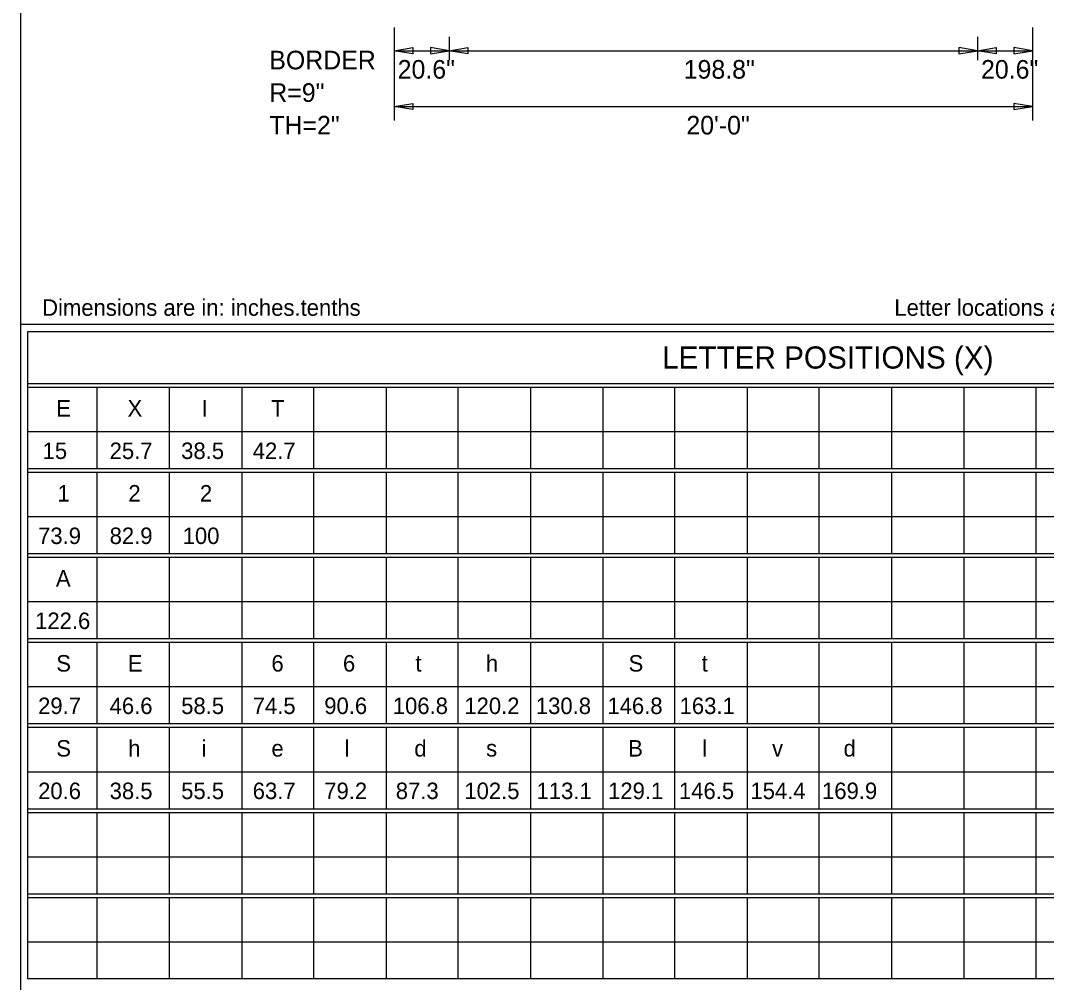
# Model space of a CAD drawing. Extents: x 2149934 to 2150188, y 145113 to 145238.
# Drawn here: x 2150076.32 to 2150108.47, y 145167.07 to 145197.23 of the extents above; entities that cross this region are included whole.
import ezdxf

# ---------------------------------------------------------------- set-up
doc = ezdxf.new("R2010")
doc.units = 0
doc.layers.add('GSDIMS', color=7, linetype='Continuous')
doc.layers.add('Level 1', color=7, linetype='Continuous')

msp = doc.modelspace()

# ---------------------------------------------------------------- linework, layer by layer
at = {"layer": 'GSDIMS'}
for p, q in [((2150088.029, 145197.007), (2150088.029, 145194.09)), ((2150108.029, 145197.007), (2150108.029, 145194.09)), ((2150088.029, 145196.715), (2150088.029, 145195.986)), ((2150089.747, 145196.715), (2150089.747, 145195.986)), ((2150089.747, 145196.715), (2150089.747, 145195.986)), ((2150106.31, 145196.715), (2150106.31, 145195.986)), ((2150106.31, 145196.715), (2150106.31, 145195.986)), ((2150108.029, 145196.715), (2150108.029, 145195.986)), ((2150088.029, 145196.278), (2150089.747, 145196.278)), ((2150089.747, 145196.278), (2150106.31, 145196.278)), ((2150106.31, 145196.278), (2150108.029, 145196.278)), ((2150088.029, 145194.965), (2150088.029, 145194.236)), ((2150108.029, 145194.965), (2150108.029, 145194.236)), ((2150088.029, 145194.528), (2150108.029, 145194.528))]:
    msp.add_line(p, q, dxfattribs=at)
for points in [[(2150088.029, 145196.278), (2150088.612, 145196.375), (2150088.612, 145196.181)], [(2150089.747, 145196.278), (2150089.164, 145196.375), (2150089.164, 145196.181)], [(2150089.747, 145196.278), (2150090.331, 145196.375), (2150090.331, 145196.181)], [(2150106.31, 145196.278), (2150105.727, 145196.375), (2150105.727, 145196.181)], [(2150106.31, 145196.278), (2150106.893, 145196.375), (2150106.893, 145196.181)], [(2150108.029, 145196.278), (2150107.445, 145196.375), (2150107.445, 145196.181)], [(2150088.029, 145194.528), (2150088.612, 145194.625), (2150088.612, 145194.431)], [(2150108.029, 145194.528), (2150107.445, 145194.625), (2150107.445, 145194.431)]]:
    msp.add_lwpolyline(points, close=True, dxfattribs=at)
at = {"layer": 'Level 1'}
for p, q in [((2150076.316, 145216.512), (2150076.316, 145117.388)), ((2150076.316, 145187.705), (2150121.342, 145187.705)), ((2150076.548, 145185.849), (2150134.843, 145185.849)), ((2150076.548, 145185.733), (2150134.843, 145185.733)), ((2150078.704, 145185.733), (2150078.704, 145183.183)), ((2150080.977, 145185.733), (2150080.977, 145183.183)), ((2150083.25, 145185.733), (2150083.25, 145183.183)), ((2150085.499, 145185.733), (2150085.499, 145183.183)), ((2150087.772, 145185.733), (2150087.772, 145183.183)), ((2150090.021, 145185.733), (2150090.021, 145183.183)), ((2150092.294, 145185.733), (2150092.294, 145183.183)), ((2150094.566, 145185.733), (2150094.566, 145183.183)), ((2150096.816, 145185.733), (2150096.816, 145183.183)), ((2150099.088, 145185.733), (2150099.088, 145183.183)), ((2150101.337, 145185.733), (2150101.337, 145183.183)), ((2150103.61, 145185.733), (2150103.61, 145183.183)), ((2150105.883, 145185.733), (2150105.883, 145183.183)), ((2150108.132, 145185.733), (2150108.132, 145183.183)), ((2150076.548, 145184.342), (2150126.185, 145184.342)), ((2150076.548, 145183.183), (2150134.843, 145183.183)), ((2150076.548, 145183.067), (2150134.843, 145183.067)), ((2150078.704, 145183.067), (2150078.704, 145180.516)), ((2150080.977, 145183.067), (2150080.977, 145180.516)), ((2150083.25, 145183.067), (2150083.25, 145180.516)), ((2150085.499, 145183.067), (2150085.499, 145180.516)), ((2150087.772, 145183.067), (2150087.772, 145180.516)), ((2150090.021, 145183.067), (2150090.021, 145180.516)), ((2150092.294, 145183.067), (2150092.294, 145180.516)), ((2150094.566, 145183.067), (2150094.566, 145180.516)), ((2150096.816, 145183.067), (2150096.816, 145180.516)), ((2150099.088, 145183.067), (2150099.088, 145180.516)), ((2150101.337, 145183.067), (2150101.337, 145180.516)), ((2150103.61, 145183.067), (2150103.61, 145180.516)), ((2150105.883, 145183.067), (2150105.883, 145180.516)), ((2150108.132, 145183.067), (2150108.132, 145180.516)), ((2150076.548, 145181.675), (2150126.185, 145181.675)), ((2150076.548, 145180.516), (2150134.843, 145180.516)), ((2150076.548, 145180.4), (2150134.843, 145180.4)), ((2150078.704, 145180.4), (2150078.704, 145177.849)), ((2150080.977, 145180.4), (2150080.977, 145177.849)), ((2150083.25, 145180.4), (2150083.25, 145177.849)), ((2150085.499, 145180.4), (2150085.499, 145177.849)), ((2150087.772, 145180.4), (2150087.772, 145177.849)), ((2150090.021, 145180.4), (2150090.021, 145177.849)), ((2150092.294, 145180.4), (2150092.294, 145177.849)), ((2150094.566, 145180.4), (2150094.566, 145177.849)), ((2150096.816, 145180.4), (2150096.816, 145177.849)), ((2150099.088, 145180.4), (2150099.088, 145177.849)), ((2150101.337, 145180.4), (2150101.337, 145177.849)), ((2150103.61, 145180.4), (2150103.61, 145177.849)), ((2150105.883, 145180.4), (2150105.883, 145177.849)), ((2150108.132, 145180.4), (2150108.132, 145177.849)), ((2150076.548, 145179.008), (2150126.185, 145179.008)), ((2150076.548, 145177.849), (2150134.843, 145177.849)), ((2150076.548, 145177.733), (2150134.843, 145177.733)), ((2150078.704, 145177.733), (2150078.704, 145175.182)), ((2150080.977, 145177.733), (2150080.977, 145175.182)), ((2150083.25, 145177.733), (2150083.25, 145175.182)), ((2150085.499, 145177.733), (2150085.499, 145175.182)), ((2150087.772, 145177.733), (2150087.772, 145175.182)), ((2150090.021, 145177.733), (2150090.021, 145175.182)), ((2150092.294, 145177.733), (2150092.294, 145175.182)), ((2150094.566, 145177.733), (2150094.566, 145175.182)), ((2150096.816, 145177.733), (2150096.816, 145175.182)), ((2150099.088, 145177.733), (2150099.088, 145175.182)), ((2150101.337, 145177.733), (2150101.337, 145175.182)), ((2150103.61, 145177.733), (2150103.61, 145175.182)), ((2150105.883, 145177.733), (2150105.883, 145175.182)), ((2150108.132, 145177.733), (2150108.132, 145175.182)), ((2150076.548, 145176.342), (2150126.185, 145176.342)), ((2150076.548, 145175.182), (2150134.843, 145175.182)), ((2150076.548, 145175.066), (2150134.843, 145175.066)), ((2150078.704, 145175.066), (2150078.704, 145172.515)), ((2150080.977, 145175.066), (2150080.977, 145172.515)), ((2150083.25, 145175.066), (2150083.25, 145172.515)), ((2150085.499, 145175.066), (2150085.499, 145172.515)), ((2150087.772, 145175.066), (2150087.772, 145172.515)), ((2150090.021, 145175.066), (2150090.021, 145172.515)), ((2150092.294, 145175.066), (2150092.294, 145172.515)), ((2150094.566, 145175.066), (2150094.566, 145172.515)), ((2150096.816, 145175.066), (2150096.816, 145172.515)), ((2150099.088, 145175.066), (2150099.088, 145172.515)), ((2150101.337, 145175.066), (2150101.337, 145172.515)), ((2150103.61, 145175.066), (2150103.61, 145172.515)), ((2150105.883, 145175.066), (2150105.883, 145172.515)), ((2150108.132, 145175.066), (2150108.132, 145172.515)), ((2150076.548, 145173.675), (2150126.185, 145173.675)), ((2150076.548, 145172.515), (2150134.843, 145172.515)), ((2150076.548, 145172.399), (2150134.843, 145172.399)), ((2150078.704, 145172.399), (2150078.704, 145169.849)), ((2150080.977, 145172.399), (2150080.977, 145169.849)), ((2150083.25, 145172.399), (2150083.25, 145169.849)), ((2150085.499, 145172.399), (2150085.499, 145169.849)), ((2150087.772, 145172.399), (2150087.772, 145169.849)), ((2150090.021, 145172.399), (2150090.021, 145169.849)), ((2150092.294, 145172.399), (2150092.294, 145169.849)), ((2150094.566, 145172.399), (2150094.566, 145169.849)), ((2150096.816, 145172.399), (2150096.816, 145169.849)), ((2150099.088, 145172.399), (2150099.088, 145169.849)), ((2150101.337, 145172.399), (2150101.337, 145169.849)), ((2150103.61, 145172.399), (2150103.61, 145169.849)), ((2150105.883, 145172.399), (2150105.883, 145169.849)), ((2150108.132, 145172.399), (2150108.132, 145169.849)), ((2150076.548, 145171.008), (2150126.185, 145171.008)), ((2150076.548, 145169.849), (2150134.843, 145169.849)), ((2150076.548, 145169.733), (2150134.843, 145169.733)), ((2150078.704, 145169.733), (2150078.704, 145167.182)), ((2150080.977, 145169.733), (2150080.977, 145167.182)), ((2150083.25, 145169.733), (2150083.25, 145167.182)), ((2150085.499, 145169.733), (2150085.499, 145167.182)), ((2150087.772, 145169.733), (2150087.772, 145167.182)), ((2150090.021, 145169.733), (2150090.021, 145167.182)), ((2150092.294, 145169.733), (2150092.294, 145167.182)), ((2150094.566, 145169.733), (2150094.566, 145167.182)), ((2150096.816, 145169.733), (2150096.816, 145167.182)), ((2150099.088, 145169.733), (2150099.088, 145167.182)), ((2150101.337, 145169.733), (2150101.337, 145167.182)), ((2150103.61, 145169.733), (2150103.61, 145167.182)), ((2150105.883, 145169.733), (2150105.883, 145167.182)), ((2150108.132, 145169.733), (2150108.132, 145167.182)), ((2150076.548, 145168.341), (2150126.185, 145168.341))]:
    msp.add_line(p, q, dxfattribs=at)
msp.add_lwpolyline([(2150076.548, 145187.473), (2150134.843, 145187.473), (2150134.843, 145167.182), (2150076.548, 145167.182)], close=True, dxfattribs=at)

# ---------------------------------------------------------------- texts
at = {"layer": 'GSDIMS'}
for s, p in [('BORDER', (2150084.112, 145195.695)), ('20.6"', (2150088.136, 145195.403)), ('198.8"', (2150097.1, 145195.403)), ('20.6"', (2150106.417, 145195.403)), ('R=9"', (2150084.112, 145194.674)), ('TH=2"', (2150084.112, 145193.653)), ('20\'-0"', (2150097.183, 145193.653))]:
    msp.add_text(s, height=0.5833, dxfattribs=at).set_placement(p)
at = {"layer": 'Level 1'}
for s, height, p in [('Dimensions are in: inches.tenths', 0.51652, (2150076.993, 145187.968)), ('Letter locations are panel edge to lower left corner', 0.51652, (2150103.701, 145187.968)), ('LETTER POSITIONS (X)', 0.69555, (2150096.422, 145186.313)), ('E', 0.517, (2150077.437, 145184.81)), ('X', 0.517, (2150079.67, 145184.81)), ('I', 0.517, (2150081.989, 145184.81)), ('T', 0.517, (2150084.167, 145184.81)), ('15', 0.5165, (2150077.008, 145183.478)), ('25.7', 0.5165, (2150079.109, 145183.478)), ('38.5', 0.5165, (2150081.351, 145183.478)), ('42.7', 0.5165, (2150083.593, 145183.478)), ('1', 0.517, (2150077.474, 145182.145)), ('2', 0.517, (2150079.695, 145182.145)), ('2', 0.517, (2150081.937, 145182.145)), ('73.9', 0.5165, (2150076.867, 145180.812)), ('82.9', 0.5165, (2150079.109, 145180.813)), ('100', 0.5165, (2150081.398, 145180.813)), ('A', 0.517, (2150077.425, 145179.479)), ('122.6', 0.5165, (2150076.773, 145178.147)), ('S', 0.517, (2150077.437, 145176.814)), ('E', 0.517, (2150079.679, 145176.814)), ('6', 0.517, (2150084.179, 145176.814)), ('6', 0.517, (2150086.421, 145176.814)), ('t', 0.517, (2150088.693, 145176.814)), ('h', 0.517, (2150090.9, 145176.814)), ('S', 0.517, (2150095.372, 145176.814)), ('t', 0.517, (2150097.661, 145176.814)), ('29.7', 0.5165, (2150076.867, 145175.482)), ('46.6', 0.5165, (2150079.109, 145175.482)), ('58.5', 0.5165, (2150081.351, 145175.482)), ('74.5', 0.5165, (2150083.593, 145175.482)), ('90.6', 0.5165, (2150085.835, 145175.482)), ('106.8', 0.5165, (2150087.983, 145175.482)), ('120.2', 0.5165, (2150090.225, 145175.482)), ('130.8', 0.5165, (2150092.467, 145175.482)), ('146.8', 0.5165, (2150094.709, 145175.482)), ('163.1', 0.5165, (2150096.972, 145175.482)), ('S', 0.517, (2150077.437, 145174.148)), ('h', 0.517, (2150079.69, 145174.148)), ('i', 0.517, (2150081.989, 145174.148)), ('e', 0.517, (2150084.179, 145174.148)), ('l', 0.517, (2150086.473, 145174.148)), ('d', 0.517, (2150088.658, 145174.148)), ('s', 0.517, (2150090.907, 145174.149)), ('B', 0.517, (2150095.361, 145174.149)), ('l', 0.517, (2150097.682, 145174.149)), ('v', 0.517, (2150099.869, 145174.149)), ('d', 0.517, (2150102.11, 145174.149)), ('20.6', 0.5165, (2150076.867, 145172.816)), ('38.5', 0.5165, (2150079.109, 145172.816)), ('55.5', 0.5165, (2150081.351, 145172.816)), ('63.7', 0.5165, (2150083.593, 145172.816)), ('79.2', 0.5165, (2150085.835, 145172.816)), ('87.3', 0.5165, (2150088.077, 145172.816)), ('102.5', 0.5165, (2150090.225, 145172.816)), ('113.1', 0.5165, (2150092.488, 145172.816)), ('129.1', 0.5165, (2150094.73, 145172.816)), ('146.5', 0.5165, (2150096.951, 145172.816)), ('154.4', 0.5165, (2150099.19, 145172.816)), ('169.9', 0.5165, (2150101.435, 145172.817))]:
    msp.add_text(s, height=height, dxfattribs=at).set_placement(p)

doc.saveas('drawing.dxf')
